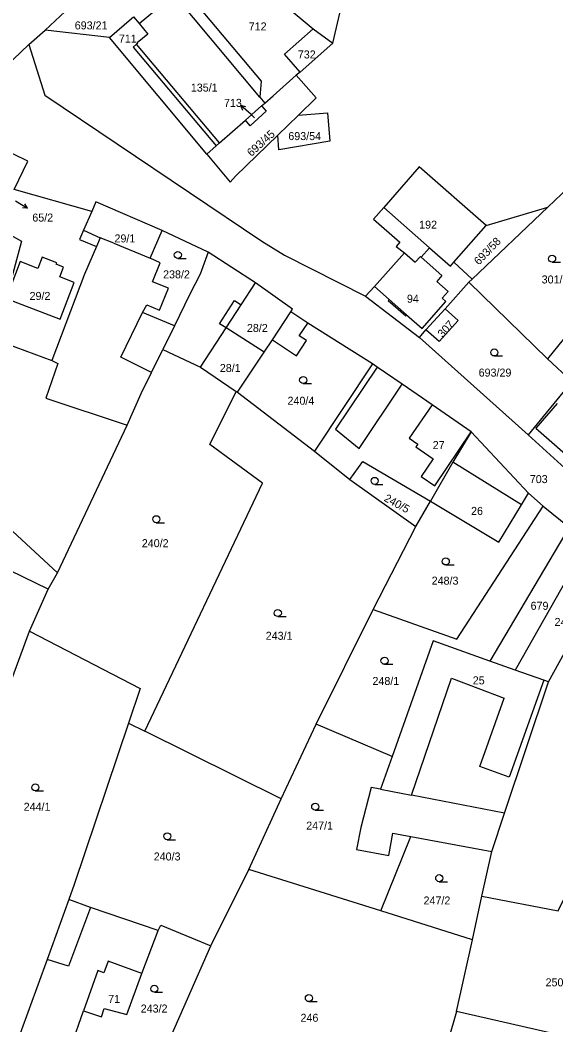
# Model space of a CAD drawing. Extents: x -7483133 to -743169, y -11317770 to -1127091.
# Drawn here: x -746514.8 to -746401, y -1132302.3 to -1132088.9 of the extents above; entities that cross this region are included whole.
import ezdxf

# ---------------------------------------------------------------- set-up
doc = ezdxf.new("R2010")
doc.units = 0
for name, color, linetype in [('Hranice parcel', 7, 'Continuous'), ('Parcelní čísla', 7, 'Continuous'), ('Pop  PČ popisy', 7, 'Continuous'), ('Vnitřní kresba', 7, 'Continuous'), ('Značky kultur', 7, 'Continuous')]:
    doc.layers.add(name, color=color, linetype=linetype)

msp = doc.modelspace()

# ---------------------------------------------------------------- linework, layer by layer
at = {"layer": 'Hranice parcel'}
for p, q in [((-746448.34, -1132093.81), (-746443.05, -1132071.26)), ((-746509.43, -1132091.08), (-746498.03, -1132080.35)), ((-746461.32, -1132083.39), (-746452.55, -1132090.79)), ((-746495.78, -1132092.58), (-746491.11, -1132088.59)), ((-746512.89, -1132094.09), (-746509.43, -1132091.08)), ((-746495.78, -1132092.58), (-746509.43, -1132091.08)), ((-746452.55, -1132090.79), (-746448.34, -1132093.81)), ((-746475.1, -1132117.39), (-746495.78, -1132092.58)), ((-746448.34, -1132093.81), (-746455.29, -1132099.94)), ((-746455.29, -1132099.94), (-746456.1, -1132100.64)), ((-746466.92, -1132110.18), (-746463.47, -1132107.14)), ((-746463.47, -1132107.14), (-746462.8, -1132106.55)), ((-746460.04, -1132113.37), (-746455.62, -1132109.09)), ((-746473.11, -1132115.64), (-746475.1, -1132117.39)), ((-746499.55, -1132129.55), (-746515.99, -1132124.9)), ((-746398.24, -1132124.43), (-746402.67, -1132128.64)), ((-746402.67, -1132128.64), (-746418.74, -1132143.92)), ((-746415.8, -1132132.54), (-746402.67, -1132128.64)), ((-746422.65, -1132140.36), (-746415.8, -1132132.54)), ((-746474.8, -1132138.2), (-746484.6, -1132133.59)), ((-746383.2, -1132136.66), (-746402.78, -1132160.86)), ((-746464.75, -1132144.73), (-746474.8, -1132138.2)), ((-746433.12, -1132138.33), (-746439.53, -1132145.49)), ((-746418.74, -1132143.92), (-746422.65, -1132140.36)), ((-746439.53, -1132145.49), (-746441.38, -1132147.52)), ((-746424.49, -1132150.27), (-746419.45, -1132144.58)), ((-746419.45, -1132144.58), (-746418.74, -1132143.92)), ((-746419.45, -1132144.58), (-746402.78, -1132160.86)), ((-746441.38, -1132147.52), (-746429.95, -1132156.33)), ((-746428.57, -1132154.69), (-746424.49, -1132150.27)), ((-746481.98, -1132153.82), (-746484.47, -1132158.9)), ((-746439.9, -1132161.92), (-746453.69, -1132153.29)), ((-746429.95, -1132156.33), (-746428.57, -1132154.69)), ((-746429.95, -1132156.33), (-746406.86, -1132176.98)), ((-746468.6, -1132167.97), (-746462.92, -1132159.41)), ((-746439.9, -1132161.92), (-746452.21, -1132180.46)), ((-746402.78, -1132160.86), (-746397.61, -1132165.68)), ((-746397.61, -1132165.68), (-746406.86, -1132176.98)), ((-746468.85, -1132167.8), (-746468.6, -1132167.97)), ((-746468.6, -1132167.97), (-746452.21, -1132180.46)), ((-746506.79, -1132206.34), (-746492.01, -1132174.94)), ((-746406.82, -1132189.39), (-746418.95, -1132176.36)), ((-746406.86, -1132176.98), (-746397.51, -1132185.52)), ((-746508.81, -1132209.8), (-746568.17, -1132180.98)), ((-746452.21, -1132180.46), (-746444.75, -1132186.48)), ((-746444.75, -1132186.48), (-746430.73, -1132196.48)), ((-746406.82, -1132189.39), (-746403.66, -1132192.14)), ((-746430.73, -1132196.48), (-746427.61, -1132191.08)), ((-746403.66, -1132192.14), (-746398.19, -1132196.61)), ((-746439.77, -1132214.12), (-746430.73, -1132196.48)), ((-746398.19, -1132196.61), (-746414.98, -1132225.06)), ((-746394.06, -1132199.47), (-746409.61, -1132226.97)), ((-746402.53, -1132229.49), (-746387.86, -1132202.51)), ((-746508.81, -1132209.8), (-746506.79, -1132206.34)), ((-746512.76, -1132218.71), (-746508.81, -1132209.8)), ((-746451.89, -1132238.47), (-746439.77, -1132214.12)), ((-746530.27, -1132265.98), (-746512.76, -1132218.71)), ((-746409.61, -1132226.97), (-746414.98, -1132225.06)), ((-746491.71, -1132238.23), (-746488.24, -1132239.95)), ((-746459.31, -1132254.28), (-746451.89, -1132238.47)), ((-746435.76, -1132245.3), (-746451.89, -1132238.47)), ((-746459.31, -1132254.28), (-746488.24, -1132239.95)), ((-746466.16, -1132269.31), (-746459.31, -1132254.28)), ((-746438.16, -1132278.12), (-746431.77, -1132262.32)), ((-746435.59, -1132261.62), (-746431.77, -1132262.32)), ((-746431.77, -1132262.32), (-746414.59, -1132265.47)), ((-746416.68, -1132275.01), (-746414.59, -1132265.47)), ((-746474.28, -1132285.54), (-746466.16, -1132269.31)), ((-746438.16, -1132278.12), (-746466.16, -1132269.31)), ((-746418.66, -1132284.23), (-746416.68, -1132275.01)), ((-746418.66, -1132284.23), (-746438.16, -1132278.12)), ((-746488.87, -1132291.4), (-746485.44, -1132282.28)), ((-746422.09, -1132299.47), (-746418.66, -1132284.23)), ((-746503.94, -1132306.81), (-746501.31, -1132299.32)), ((-746398.2, -1132304.9), (-746422.09, -1132299.47))]:
    msp.add_line(p, q, dxfattribs=at)
for points in [[(-746489.5, -1132089.65), (-746482.1, -1132083.45), (-746480.34, -1132081.97), (-746478.97, -1132083.6), (-746475.62, -1132087.56)], [(-746475.62, -1132087.56), (-746463.55, -1132101.86), (-746463.86, -1132105.28), (-746462.8, -1132106.55)], [(-746491.11, -1132088.59), (-746490.68, -1132088.23), (-746489.5, -1132089.65)], [(-746489.5, -1132089.65), (-746487.65, -1132091.87), (-746489.91, -1132093.76), (-746489.82, -1132093.88), (-746490.01, -1132094.04), (-746490.73, -1132094.66), (-746473.11, -1132115.64)], [(-746455.29, -1132099.94), (-746458.63, -1132096.15), (-746452.55, -1132090.79)], [(-746577.11, -1132104.01), (-746568.02, -1132102.18), (-746541.34, -1132105.39), (-746522.96, -1132103.62), (-746512.89, -1132094.09)], [(-746512.89, -1132094.09), (-746509.52, -1132104.89), (-746463.45, -1132135.88), (-746458.58, -1132138.82), (-746441.38, -1132147.52)], [(-746462.8, -1132106.55), (-746461.02, -1132104.98), (-746456.1, -1132100.64)], [(-746455.62, -1132109.09), (-746451.86, -1132105.45), (-746456.1, -1132100.64)], [(-746463.47, -1132107.14), (-746462.48, -1132108.27), (-746465.9, -1132111.34), (-746466.92, -1132110.18)], [(-746455.62, -1132109.09), (-746449.46, -1132108.64), (-746448.96, -1132114.63), (-746459.82, -1132116.44), (-746460.04, -1132113.37)], [(-746473.11, -1132115.64), (-746472.4, -1132115.01), (-746466.92, -1132110.18)], [(-746475.1, -1132117.39), (-746470.12, -1132123.36), (-746469.01, -1132122.04), (-746460.04, -1132113.37)], [(-746515.99, -1132124.9), (-746513.12, -1132118.91), (-746521.86, -1132114.62), (-746524.85, -1132120.71), (-746522.77, -1132121.69), (-746523.8, -1132123.84)], [(-746415.8, -1132132.54), (-746430, -1132120.09), (-746437.54, -1132128.72), (-746439.72, -1132131.22), (-746434.15, -1132136.09), (-746434.93, -1132136.99), (-746433.12, -1132138.33)], [(-746484.6, -1132133.59), (-746498.66, -1132127.5), (-746499.55, -1132129.55)], [(-746526.85, -1132128.93), (-746514.46, -1132135.87), (-746517.68, -1132148.02), (-746519.55, -1132156.97), (-746508.03, -1132161.18)], [(-746499.55, -1132129.55), (-746501.28, -1132133.56), (-746497.76, -1132135.18), (-746498.53, -1132136.98), (-746501.07, -1132142.89), (-746508.03, -1132161.18)], [(-746481.98, -1132153.82), (-746488.73, -1132150.99), (-746487.86, -1132149.42), (-746485.17, -1132150.55), (-746483.26, -1132145.87), (-746486.65, -1132144.48), (-746485, -1132140.49), (-746487.14, -1132139.46), (-746484.6, -1132133.59)], [(-746474.8, -1132138.2), (-746476.52, -1132142.87), (-746478.77, -1132147.26), (-746481.98, -1132153.82)], [(-746433.12, -1132138.33), (-746430.85, -1132140.35), (-746429.75, -1132139.12), (-746429.6, -1132139.26), (-746427.83, -1132137.27), (-746423.38, -1132141.19), (-746422.65, -1132140.36)], [(-746462.92, -1132159.41), (-746471.01, -1132154.29), (-746467.81, -1132149.4), (-746464.75, -1132144.73)], [(-746453.69, -1132153.29), (-746457.28, -1132150.91), (-746456.89, -1132150.33), (-746464.75, -1132144.73)], [(-746424.49, -1132150.27), (-746421.7, -1132152.74), (-746425.77, -1132157.17), (-746428.57, -1132154.69)], [(-746456.05, -1132160.19), (-746453.92, -1132156.98), (-746455.46, -1132155.96), (-746453.69, -1132153.29)], [(-746462.92, -1132159.41), (-746461.18, -1132156.79), (-746456.05, -1132160.19)], [(-746492.01, -1132174.94), (-746489.02, -1132168.19), (-746486.86, -1132163.77), (-746484.47, -1132158.9)], [(-746484.47, -1132158.9), (-746476.47, -1132162.64), (-746468.85, -1132167.8)], [(-746508.03, -1132161.18), (-746506.73, -1132161.88), (-746509.28, -1132169.18), (-746492.01, -1132174.94)], [(-746433.6, -1132166.24), (-746438.91, -1132162.6), (-746439.9, -1132161.92)], [(-746418.95, -1132176.36), (-746427.27, -1132170.61), (-746433.6, -1132166.24)], [(-746488.24, -1132239.95), (-746463.28, -1132187.24), (-746474.43, -1132179.05), (-746468.85, -1132167.8)], [(-746506.79, -1132206.34), (-746525.9, -1132188.66), (-746565.04, -1132174.52)], [(-746418.95, -1132176.36), (-746422.87, -1132182.82), (-746427.61, -1132191.08)], [(-746444.75, -1132186.48), (-746441.98, -1132182.67), (-746427.61, -1132191.08)], [(-746427.61, -1132191.08), (-746413.07, -1132199.82), (-746408.27, -1132191.87), (-746406.82, -1132189.39)], [(-746439.77, -1132214.12), (-746422.02, -1132220.4), (-746413.23, -1132206.88), (-746403.66, -1132192.14)], [(-746512.76, -1132218.71), (-746489.23, -1132230.86), (-746491.71, -1132238.23)], [(-746414.98, -1132225.06), (-746427.06, -1132220.77), (-746435.76, -1132245.3)], [(-746402.53, -1132229.49), (-746403.57, -1132229.12), (-746409.61, -1132226.97)], [(-746414.59, -1132265.47), (-746411.87, -1132257.36), (-746402.53, -1132229.49)], [(-746491.71, -1132238.23), (-746503.25, -1132272.52), (-746504.41, -1132275.72)], [(-746435.76, -1132245.3), (-746438.24, -1132252.29), (-746440.19, -1132251.91), (-746442.43, -1132260.37), (-746443.3, -1132265.09)], [(-746443.3, -1132265.09), (-746436.46, -1132266.34), (-746435.59, -1132261.62)], [(-746504.41, -1132275.72), (-746509.03, -1132288.43), (-746514.75, -1132304.17)], [(-746485.44, -1132282.28), (-746499.8, -1132277.41), (-746504.41, -1132275.72)], [(-746416.68, -1132275.01), (-746400.51, -1132278.11), (-746398.85, -1132274.79)], [(-746485.44, -1132282.28), (-746484.89, -1132281.12), (-746474.28, -1132285.54)], [(-746485.44, -1132312.39), (-746483.4, -1132306.31), (-746474.28, -1132285.54)], [(-746501.31, -1132299.32), (-746497.49, -1132300.63), (-746496.87, -1132298.83), (-746492.06, -1132300.12), (-746488.87, -1132291.4)], [(-746422.09, -1132299.47), (-746423.86, -1132305.66), (-746427.94, -1132325.8)]]:
    msp.add_lwpolyline(points, dxfattribs=at)
at = {"layer": 'Pop  PČ popisy'}
for p, q in [((-746465.7, -1132108.98), (-746467.96, -1132107.01)), ((-746467.96, -1132107.01), (-746466.88, -1132107.29)), ((-746467.96, -1132107.01), (-746467.54, -1132108.05)), ((-746464.95, -1132109.64), (-746465.7, -1132108.98)), ((-746515.7, -1132127.28), (-746513.16, -1132128.87)), ((-746513.16, -1132128.87), (-746513.74, -1132127.92)), ((-746513.16, -1132128.87), (-746514.27, -1132128.76))]:
    msp.add_line(p, q, dxfattribs=at)
at = {"layer": 'Vnitřní kresba'}
for p, q in [((-746463.86, -1132105.28), (-746482.1, -1132083.45)), ((-746472.4, -1132115.01), (-746490.01, -1132094.04)), ((-746437.54, -1132128.72), (-746427.83, -1132137.27)), ((-746501.28, -1132133.56), (-746502.12, -1132135.48)), ((-746502.12, -1132135.48), (-746498.53, -1132136.98)), ((-746494.82, -1132136.26), (-746497.76, -1132135.18)), ((-746494.82, -1132136.26), (-746487.14, -1132139.46)), ((-746514.71, -1132140.21), (-746517.68, -1132148.02)), ((-746510.97, -1132141.65), (-746514.71, -1132140.21)), ((-746510.06, -1132139.27), (-746510.97, -1132141.65)), ((-746506.97, -1132140.46), (-746510.06, -1132139.27)), ((-746507.1, -1132140.78), (-746506.97, -1132140.46)), ((-746505.51, -1132141.4), (-746507.1, -1132140.78)), ((-746429.6, -1132139.26), (-746425.18, -1132143.19)), ((-746506.31, -1132143.45), (-746505.51, -1132141.4)), ((-746503.27, -1132144.62), (-746506.31, -1132143.45)), ((-746425.18, -1132143.19), (-746426.28, -1132144.42)), ((-746506.28, -1132152.42), (-746503.27, -1132144.62)), ((-746439.53, -1132145.49), (-746436.41, -1132148.24)), ((-746426.28, -1132144.42), (-746423.89, -1132146.55)), ((-746425.15, -1132147.97), (-746423.89, -1132146.55)), ((-746517.68, -1132148.02), (-746506.28, -1132152.42)), ((-746472.4, -1132153.39), (-746469.22, -1132148.47)), ((-746469.22, -1132148.47), (-746467.81, -1132149.4)), ((-746436.41, -1132148.24), (-746436.59, -1132148.45)), ((-746436.59, -1132148.45), (-746432.87, -1132151.74)), ((-746432.68, -1132151.53), (-746436.41, -1132148.24)), ((-746429.39, -1132154.44), (-746424.32, -1132148.7)), ((-746424.32, -1132148.7), (-746425.15, -1132147.97)), ((-746493.39, -1132160.49), (-746488.73, -1132150.99)), ((-746461.18, -1132156.79), (-746457.28, -1132150.91)), ((-746432.87, -1132151.74), (-746432.68, -1132151.53)), ((-746432.68, -1132151.53), (-746429.39, -1132154.44)), ((-746471.01, -1132154.29), (-746472.4, -1132153.39)), ((-746476.47, -1132162.64), (-746471.01, -1132154.29)), ((-746486.86, -1132163.77), (-746493.39, -1132160.49)), ((-746438.91, -1132162.6), (-746447.75, -1132175.82)), ((-746442.73, -1132179.87), (-746433.6, -1132166.24)), ((-746400.72, -1132170.37), (-746405.23, -1132175.59)), ((-746447.75, -1132175.82), (-746442.73, -1132179.87)), ((-746405.23, -1132175.59), (-746395.9, -1132183.77)), ((-746408.27, -1132191.87), (-746422.87, -1132182.82)), ((-746431.66, -1132253.55), (-746423.15, -1132228.66)), ((-746423.15, -1132228.66), (-746411.94, -1132232.94)), ((-746403.57, -1132229.12), (-746410.88, -1132249.69)), ((-746417.11, -1132247.47), (-746411.94, -1132232.94)), ((-746410.88, -1132249.69), (-746417.11, -1132247.47)), ((-746438.24, -1132252.29), (-746431.66, -1132253.55)), ((-746411.87, -1132257.36), (-746431.66, -1132253.55)), ((-746499.8, -1132277.41), (-746504.5, -1132289.85)), ((-746504.5, -1132289.85), (-746509.03, -1132288.43)), ((-746496.04, -1132288.78), (-746496.95, -1132291.26)), ((-746488.87, -1132291.4), (-746496.04, -1132288.78)), ((-746498.22, -1132290.8), (-746501.31, -1132299.32)), ((-746496.95, -1132291.26), (-746498.22, -1132290.8))]:
    msp.add_line(p, q, dxfattribs=at)
msp.add_lwpolyline([(-746427.27, -1132170.61), (-746432.16, -1132177.73), (-746430.31, -1132178.99), (-746430.7, -1132179.57), (-746427.03, -1132182.07), (-746429.6, -1132185.84), (-746426.7, -1132187.81), (-746418.95, -1132176.36)], dxfattribs=at)
at = {"layer": 'Značky kultur'}
for p, q in [((-746481.26, -1132139.54), (-746479.51, -1132139.54)), ((-746401.78, -1132140.35), (-746400.03, -1132140.35)), ((-746414.05, -1132160.25), (-746412.3, -1132160.25)), ((-746454.64, -1132166.12), (-746452.89, -1132166.12)), ((-746439.46, -1132187.53), (-746437.71, -1132187.53)), ((-746485.83, -1132195.67), (-746484.08, -1132195.67)), ((-746424.36, -1132204.64), (-746422.61, -1132204.64)), ((-746460.03, -1132215.6), (-746458.28, -1132215.6)), ((-746437.37, -1132225.74), (-746435.62, -1132225.74)), ((-746511.53, -1132252.63), (-746509.78, -1132252.63)), ((-746452.08, -1132256.74), (-746450.33, -1132256.74)), ((-746483.5, -1132263.01), (-746481.75, -1132263.01)), ((-746425.75, -1132271.91), (-746424, -1132271.91)), ((-746486.25, -1132295.39), (-746484.5, -1132295.39)), ((-746453.43, -1132297.38), (-746451.68, -1132297.38))]:
    msp.add_line(p, q, dxfattribs=at)
for centre in [(-746481.26, -1132138.79), (-746401.78, -1132139.6), (-746414.05, -1132159.5), (-746454.64, -1132165.37), (-746439.46, -1132186.78), (-746485.83, -1132194.92), (-746424.36, -1132203.89), (-746460.03, -1132214.85), (-746437.37, -1132224.99), (-746511.53, -1132251.88), (-746452.08, -1132255.99), (-746483.5, -1132262.26), (-746425.75, -1132271.16), (-746486.25, -1132294.64), (-746453.43, -1132296.63)]:
    msp.add_circle(centre, 0.75, dxfattribs=at)

# ---------------------------------------------------------------- texts
at = {"layer": 'Parcelní čísla'}
for s, p in [('693/21', (-746503.15, -1132090.89)), ('712', (-746466.21, -1132091.11)), ('711', (-746493.78, -1132093.69)), ('732', (-746455.78, -1132097.06)), ('135/1', (-746478.5, -1132104.1)), ('713', (-746471.46, -1132107.35)), ('693/54', (-746457.8, -1132114.4)), ('65/2', (-746512.16, -1132131.71)), ('192', (-746430.02, -1132133.22)), ('29/1', (-746494.71, -1132136.13)), ('238/2', (-746484.39, -1132143.77)), ('301/1', (-746404, -1132144.85)), ('29/2', (-746512.74, -1132148.35)), ('94', (-746432.61, -1132148.94)), ('28/2', (-746466.59, -1132155.15)), ('28/1', (-746472.34, -1132163.65)), ('693/29', (-746417.38, -1132164.63)), ('240/4', (-746457.97, -1132170.61)), ('27', (-746427.13, -1132180.02)), ('703', (-746406.52, -1132187.25)), ('26', (-746418.99, -1132194.01)), ('240/2', (-746488.91, -1132200.86)), ('248/3', (-746427.36, -1132208.82)), ('679', (-746406.35, -1132214.16)), ('249', (-746401.26, -1132217.59)), ('243/1', (-746462.6, -1132220.53)), ('248/1', (-746439.93, -1132230.13)), ('25', (-746418.63, -1132230)), ('244/1', (-746514, -1132256.85)), ('247/1', (-746454, -1132260.85)), ('240/3', (-746486.38, -1132267.4)), ('247/2', (-746429.08, -1132276.75)), ('250/2', (-746403.17, -1132294.13)), ('71', (-746496.05, -1132297.66)), ('243/2', (-746489.14, -1132299.7)), ('246', (-746455.21, -1132301.66))]:
    msp.add_text(s, height=1.7, dxfattribs=at).set_placement(p)
for s, rotation, p in [('693/45', 42, (-746465.65, -1132118)), ('693/58', 46, (-746417.34, -1132141.06)), ('307', 47, (-746425.04, -1132156.47)), ('240/5', 331, (-746437.62, -1132190.95))]:
    msp.add_text(s, height=1.7, rotation=rotation, dxfattribs=at).set_placement(p)

doc.saveas('drawing.dxf')
